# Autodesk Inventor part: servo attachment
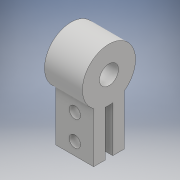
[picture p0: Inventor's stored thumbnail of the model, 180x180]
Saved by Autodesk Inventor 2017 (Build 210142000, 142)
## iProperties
Created: 2017-04
Part Number: servo attachment
Material: Generic
Document SubType Name: Modeling
Designer: s4321966
Density: 1 g/cm^3
Appearance: Default
Author: s4321966
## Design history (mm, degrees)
sketch "Sketch1" dims "d0" = 7
  geometry: L1 (0, -3.5)-(0.5, -3.5); L2 (0.5, -3.5)-(0.5, -9.5); L3 (0.5, -9.5)-(0, -9.5); L4 (0, -9.5)-(0, -3.5); L5 (0.5, -9.5)-(2.028, -9.5); L6 (2.028, -9.5)-(2.028, -1.25); L7 (2.028, -1.25)-(0.5, -1.25); L8 (0.5, -1.25)-(0.5, -9.5); L9 (0, -3.5)-(-0.5, -3.5); L10 (-0.5, -3.5)-(-0.5, -9.5); L11 (-0.5, -9.5)-(0, -9.5); L12 (-0.5, -9.5)-(-2.028, -9.5); L13 (-2.028, -9.5)-(-2.028, -1.25); L14 (-2.028, -1.25)-(-0.5, -1.25); L15 (-0.5, -1.25)-(-0.5, -9.5); C1 r 1.25 at (0, 0); 2 further points
  constraints: 30 end point, 5 symmetric about line, 4 coincident, 4 parallel, 2 horizontal, 2 perpendicular, 1 centre point, 1 vertical alignment, 2 other
  dimensions: "d1" = 2.5 diameter of C1; "d2" = 0.5 distance of L2.end L3.end; "d3" = 6 distance of L1.end L2.end
extrude "Extrusion1" new body sketch "Sketch1" distance "d4" = 5; taper "d5" = 0 deg
sketch "Sketch2"
  geometry: L1 (0, 6.647)-(5, 6.647) reference; L2 (2.5, 6.647)-(2.5, 0); L3 (5, 0)-(0, 0) reference; L4 (2.5, 3.324)-(0, 6.647); L5 (0, 6.647)-(5.07, 3.324); L6 (5.07, 3.324)-(0, 0); C1 r 0.75 at (2.535, 1.662); C2 r 0.75 at (2.535, 4.985); 1 further point
  constraints: 8 end point, 5 midpoint, 2 centre point
  dimensions: "d6" = 1.5 diameter of C1; "d7" = 1.5 diameter of C2
extrude "Extrusion2" cut sketch "Sketch2" distance "d8" = 5; taper "d9" = 0 deg
body "Solid1"
